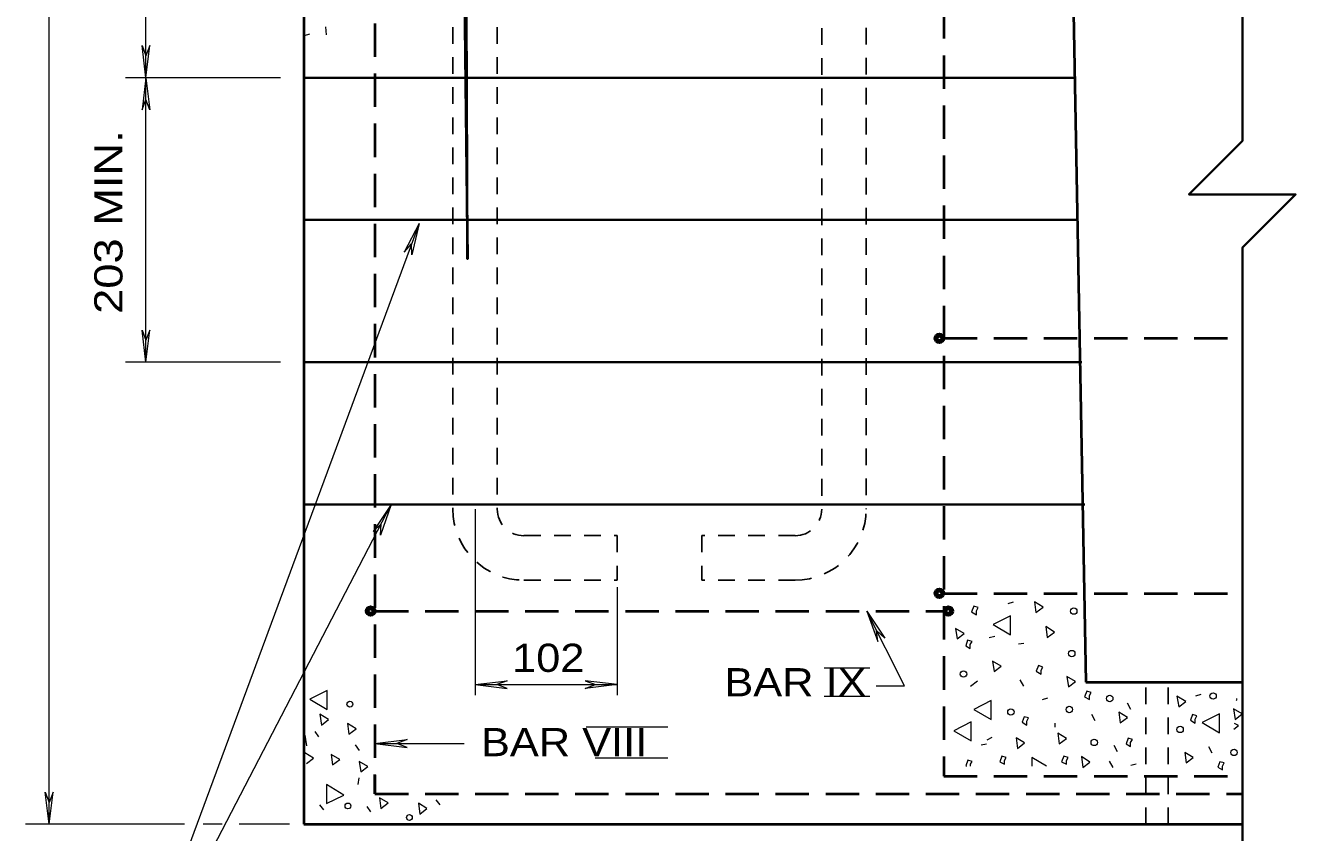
# Model space of a CAD drawing. Extents: x 312583 to 312854, y 144419 to 144597.
# Drawn here: x 312747.38 to 312781.61, y 144449.56 to 144471.31 of the extents above; entities that cross this region are included whole.
import ezdxf

# ---------------------------------------------------------------- set-up
doc = ezdxf.new("R2010")
doc.units = 0
doc.header["$LTSCALE"] = 0.3
doc.linetypes.add('MEDIUM_DASHED', pattern=[4.5, 3, -1.5])
doc.linetypes.add('SHORT_DASHED', pattern=[2.7, 1.5, -1.2])
doc.layers.add('1', color=7, linetype='Continuous', lineweight=25)
doc.layers.add('2', color=7, linetype='Continuous', lineweight=13)

msp = doc.modelspace()

# ---------------------------------------------------------------- linework, layer by layer
at = {"layer": '1', "lineweight": 40}
for p, q in [((312754.8813, 144492.4211), (312754.8813, 144449.7791)), ((312775.2517, 144491.7004), (312775.9647, 144453.6124)), ((312775.9647, 144453.6124), (312780.1813, 144453.6124)), ((312756.798, 144450.5994), (312756.798, 144451.1208)), ((312756.798, 144450.5994), (312757.626, 144450.5994)), ((312754.8813, 144449.7791), (312780.1813, 144449.7791))]:
    msp.add_line(p, q, dxfattribs=at)
at = {"layer": '1', "linetype": 'SHORT_DASHED'}
for p, q in [((312758.8987, 144491.5164), (312758.8987, 144458.2738)), ((312760.0947, 144491.5164), (312760.0947, 144458.2738)), ((312768.8423, 144489.8681), (312768.8423, 144458.2738)), ((312770.0383, 144489.8834), (312770.0383, 144458.2738)), ((312760.8153, 144457.5608), (312763.33, 144457.5608)), ((312763.33, 144457.5608), (312763.33, 144456.3571)), ((312765.607, 144457.5608), (312765.607, 144456.3571)), ((312768.1217, 144457.5608), (312765.607, 144457.5608)), ((312760.8153, 144456.3571), (312763.33, 144456.3571)), ((312768.1217, 144456.3571), (312765.607, 144456.3571)), ((312777.5823, 144449.7791), (312777.5823, 144453.5358)), ((312778.1803, 144449.7791), (312778.1803, 144453.4974))]:
    msp.add_line(p, q, dxfattribs=at)
at = {"layer": '1', "linetype": 'MEDIUM_DASHED', "lineweight": 40}
for p, q in [((312772.1313, 144490.7574), (312772.1313, 144451.0748)), ((312756.798, 144490.2668), (312756.798, 144450.5994)), ((312772.1313, 144462.8814), (312780.1813, 144462.8814)), ((312772.1313, 144456.0044), (312780.1813, 144456.0044)), ((312756.798, 144455.5291), (312772.1313, 144455.5291)), ((312772.1313, 144451.0748), (312780.1813, 144451.0748)), ((312756.798, 144450.5994), (312780.1813, 144450.5994))]:
    msp.add_line(p, q, dxfattribs=at)
at = {"layer": '1', "lineweight": 13}
for p, q in [((312754.8967, 144471.0388), (312755.0423, 144471.0848)), ((312755.464, 144471.2764), (312755.487, 144471.0618)), ((312773.864, 144455.7284), (312774.0097, 144455.7744)), ((312773.358, 144454.8161), (312773.5037, 144454.8544)), ((312774.1477, 144454.6474), (312774.2933, 144454.6628)), ((312773.036, 144453.6354), (312772.852, 144453.4974)), ((312774.186, 144453.6738), (312774.278, 144453.5051)), ((312778.924, 144453.2444), (312779.0697, 144453.2828)), ((312774.7917, 144453.1448), (312774.9373, 144453.1908)), ((312777.0763, 144453.0528), (312777.1683, 144452.8841)), ((312776.1103, 144452.7461), (312776.2023, 144452.5774)), ((312754.9043, 144452.1864), (312754.9503, 144451.8951)), ((312755.1803, 144452.2784), (312755.28, 144452.1404)), ((312775.1367, 144452.4011), (312775.1367, 144452.5084)), ((312756.2613, 144451.9181), (312756.3687, 144451.7724)), ((312773.1357, 144451.9181), (312773.2813, 144451.9488)), ((312773.3043, 144452.0561), (312773.4347, 144452.1251)), ((312776.716, 144451.9104), (312776.808, 144451.7418)), ((312779.269, 144451.8721), (312779.361, 144451.7034)), ((312774.508, 144451.5808), (312774.508, 144451.3508)), ((312774.899, 144451.3508), (312774.508, 144451.5808)), ((312772.852, 144451.3508), (312772.852, 144451.3968)), ((312776.5933, 144451.4811), (312776.6853, 144451.3124)), ((312777.176, 144451.3738), (312777.3217, 144451.4121)), ((312756.3457, 144450.8524), (312756.3687, 144451.0364)), ((312755.303, 144450.3081), (312755.4103, 144450.1701)), ((312756.5757, 144450.2621), (312756.6753, 144450.1164)), ((312758.4387, 144450.4384), (312758.546, 144450.3004))]:
    msp.add_line(p, q, dxfattribs=at)
at = {"layer": '1', "lineweight": 40}
msp.add_lwpolyline([(312758.9293, 144496.4231), (312759.2897, 144465.0204), (312759.167, 144496.3848)], dxfattribs=at)
at = {"layer": '1', "lineweight": 35}
msp.add_lwpolyline([(312780.1813, 144494.8208), (312780.1813, 144482.4621), (312778.74, 144481.0284), (312781.615, 144481.0284), (312780.1813, 144479.5871), (312780.1813, 144468.2021), (312778.74, 144466.7608), (312781.615, 144466.7608), (312780.1813, 144465.3271), (312780.1813, 144447.8624)], dxfattribs=at)
at = {"layer": '1', "lineweight": 13}
for points in [[(312757.994, 144465.9788), (312750.0999, 144444.6519), (312757.235, 144458.4041)], [(312754.9503, 144451.4198), (312755.142, 144451.5654), (312754.9043, 144451.7034)], [(312772.852, 144451.3968), (312772.898, 144451.4734), (312772.783, 144451.5118), (312772.7217, 144451.3584), (312772.7447, 144451.3508)]]:
    msp.add_lwpolyline(points, dxfattribs=at)
for points in [[(312773.013, 144455.5368), (312773.059, 144455.6211), (312772.944, 144455.6594), (312772.8827, 144455.5061), (312773.013, 144455.4294)], [(312774.6153, 144455.4908), (312774.807, 144455.6364), (312774.577, 144455.7744)], [(312773.933, 144454.8851), (312773.933, 144455.3988), (312773.4653, 144455.1611)], [(312772.4917, 144454.7778), (312772.6833, 144454.9234), (312772.4457, 144455.0614)], [(312774.922, 144454.8161), (312775.1137, 144454.9618), (312774.8837, 144455.1074)], [(312772.8443, 144454.6244), (312772.898, 144454.7088), (312772.7753, 144454.7471), (312772.7217, 144454.5938), (312772.8443, 144454.5171)], [(312773.4883, 144453.8961), (312773.68, 144454.0418), (312773.4423, 144454.1798)], [(312774.7533, 144453.9344), (312774.7993, 144454.0188), (312774.6843, 144454.0571), (312774.623, 144453.9038), (312774.7533, 144453.8271)], [(312775.4893, 144453.4821), (312775.681, 144453.6278), (312775.451, 144453.7658)], [(312755.51, 144452.8764), (312755.51, 144453.3901), (312755.0423, 144453.1524)], [(312776.0567, 144453.2521), (312776.1027, 144453.3288), (312775.9877, 144453.3671), (312775.9263, 144453.2138), (312776.0567, 144453.1448)], [(312778.464, 144452.9454), (312778.6557, 144453.0911), (312778.418, 144453.2291)], [(312773.4117, 144452.6004), (312773.4117, 144453.1141), (312772.944, 144452.8764)], [(312779.982, 144452.6081), (312780.1737, 144452.7538), (312779.9437, 144452.8918)], [(312755.3567, 144452.4548), (312755.5483, 144452.6004), (312755.3107, 144452.7461)], [(312772.8673, 144452.0254), (312772.8673, 144452.5391), (312772.3997, 144452.3014)], [(312774.37, 144452.5621), (312774.416, 144452.6464), (312774.301, 144452.6771), (312774.2473, 144452.5314), (312774.37, 144452.4548)], [(312776.8847, 144452.5161), (312777.084, 144452.6618), (312776.8463, 144452.7998)], [(312778.9087, 144452.6158), (312778.9547, 144452.7001), (312778.8397, 144452.7384), (312778.7783, 144452.5851), (312778.9087, 144452.5084)], [(312779.568, 144452.2478), (312779.568, 144452.7614), (312779.1003, 144452.5238)], [(312756.0927, 144452.2094), (312756.292, 144452.3551), (312756.0543, 144452.4931)], [(312775.244, 144451.9488), (312775.4433, 144452.0944), (312775.2057, 144452.2324)], [(312774.117, 144451.8261), (312774.3087, 144451.9718), (312774.0787, 144452.1098)], [(312777.1683, 144451.9871), (312777.2143, 144452.0638), (312777.0993, 144452.1021), (312777.0457, 144451.9488), (312777.1683, 144451.8798)], [(312755.6557, 144451.3814), (312755.8473, 144451.5271), (312755.6173, 144451.6651)], [(312773.7643, 144451.4964), (312773.8103, 144451.5808), (312773.6953, 144451.6191), (312773.6417, 144451.4658), (312773.7643, 144451.3968)], [(312775.4357, 144451.4964), (312775.4817, 144451.5808), (312775.3667, 144451.6191), (312775.3053, 144451.4658), (312775.4357, 144451.3968)], [(312775.8803, 144451.3124), (312776.072, 144451.4581), (312775.842, 144451.6038)], [(312778.6633, 144451.4351), (312778.855, 144451.5808), (312778.625, 144451.7188)], [(312756.4147, 144451.1898), (312756.6063, 144451.3354), (312756.3763, 144451.4734)], [(312779.6447, 144451.3508), (312779.6907, 144451.4351), (312779.5757, 144451.4658), (312779.522, 144451.3201), (312779.6447, 144451.2434)], [(312755.4947, 144450.8524), (312755.4947, 144450.3388), (312755.9623, 144450.5688)], [(312756.959, 144450.2008), (312757.1507, 144450.3541), (312756.9207, 144450.4921)], [(312758.0093, 144450.0551), (312758.201, 144450.2008), (312757.971, 144450.3464)]]:
    msp.add_lwpolyline(points, close=True, dxfattribs=at)
at = {"layer": '1', "lineweight": 40}
for centre, radius in [((312772.0144, 144462.8786), 0.1198), ((312772.0144, 144462.8786), 0.0838), ((312772.0144, 144462.8786), 0.0587), ((312772.0144, 144456.0054), 0.1198), ((312772.0144, 144456.0054), 0.0838), ((312772.0144, 144456.0054), 0.0587), ((312756.6811, 144455.5262), 0.1198), ((312756.6811, 144455.5262), 0.0838), ((312772.254, 144455.5262), 0.1198), ((312772.254, 144455.5262), 0.0838), ((312756.6811, 144455.5262), 0.0587), ((312772.254, 144455.5262), 0.0587)]:
    msp.add_circle(centre, radius, dxfattribs=at)
at = {"layer": '1', "lineweight": 13}
for centre, radius in [((312775.6357, 144455.5264), 0.0865), ((312775.582, 144454.3821), 0.0865), ((312772.662, 144453.8301), 0.0865), ((312776.6046, 144453.1708), 0.0865), ((312779.3904, 144453.2379), 0.0865), ((312756.1221, 144453.018), 0.0784), ((312773.9404, 144452.8076), 0.0865), ((312775.5149, 144452.8747), 0.0865), ((312778.5021, 144452.3361), 0.0865), ((312776.1877, 144451.9863), 0.0865), ((312779.9549, 144451.717), 0.0865), ((312756.0703, 144450.2734), 0.0784), ((312757.7273, 144449.9629), 0.0784)]:
    msp.add_circle(centre, radius, dxfattribs=at)
at = {"layer": '1', "linetype": 'SHORT_DASHED'}
for centre, radius, start, end in [((312760.8134, 144458.2757), 1.9167, 180, 270), ((312760.8134, 144458.2757), 0.7188, 180, 270), ((312768.1217, 144458.2757), 1.9167, 270, 0), ((312768.1217, 144458.2757), 0.7188, 270, 0)]:
    msp.add_arc(centre, radius, start, end, dxfattribs=at)
at = {"layer": '2'}
for p, q in [((312748.0197, 144449.7791), (312748.0197, 144492.9041)), ((312750.6263, 144469.9041), (312750.6263, 144492.9041)), ((312750.519, 144470.7704), (312750.6263, 144470.4944)), ((312750.6263, 144469.9041), (312750.519, 144470.7704)), ((312750.7337, 144470.7704), (312750.6263, 144470.4944)), ((312750.6263, 144469.9041), (312750.7337, 144470.7704)), ((312754.2527, 144469.9041), (312750.0743, 144469.9041)), ((312750.6263, 144469.9041), (312750.519, 144469.0378)), ((312750.6263, 144469.9041), (312750.7337, 144469.0378)), ((312750.6263, 144462.2374), (312750.6263, 144469.9041)), ((312750.519, 144469.0378), (312750.6263, 144469.3138)), ((312750.7337, 144469.0378), (312750.6263, 144469.3138)), ((312757.994, 144465.9788), (312757.5877, 144465.2044)), ((312757.994, 144465.9788), (312757.7947, 144465.1278)), ((312757.5877, 144465.2044), (312757.787, 144465.4268)), ((312757.7947, 144465.1278), (312757.787, 144465.4268)), ((312750.5189, 144463.1037), (312750.6263, 144462.8277)), ((312750.6263, 144462.2374), (312750.5189, 144463.1037)), ((312750.7336, 144463.1037), (312750.6263, 144462.8277)), ((312750.6263, 144462.2374), (312750.7336, 144463.1037)), ((312754.2527, 144462.2374), (312750.0743, 144462.2374)), ((312757.235, 144458.4041), (312756.752, 144457.6758)), ((312757.235, 144458.4041), (312756.9437, 144457.5761)), ((312759.4967, 144458.2738), (312759.4967, 144453.2598)), ((312756.752, 144457.6758), (312756.9667, 144457.8751)), ((312756.9437, 144457.5761), (312756.9667, 144457.8751)), ((312763.33, 144456.1731), (312763.33, 144453.2598)), ((312770.0537, 144455.5291), (312770.3527, 144454.7088)), ((312770.0537, 144455.5291), (312770.5443, 144454.8008)), ((312770.3527, 144454.7088), (312770.322, 144455.0001)), ((312770.5443, 144454.8008), (312770.322, 144455.0001)), ((312768.9037, 144453.9958), (312770.138, 144453.9958)), ((312759.4967, 144453.5434), (312760.363, 144453.6508)), ((312760.363, 144453.6508), (312760.087, 144453.5434)), ((312762.4637, 144453.6508), (312762.7397, 144453.5434)), ((312763.33, 144453.5434), (312762.4637, 144453.6508)), ((312759.4967, 144453.5434), (312763.33, 144453.5434)), ((312759.4967, 144453.5434), (312760.363, 144453.4361)), ((312760.363, 144453.4361), (312760.087, 144453.5434)), ((312762.4637, 144453.4361), (312762.7397, 144453.5434)), ((312763.33, 144453.5434), (312762.4637, 144453.4361)), ((312768.9037, 144453.2353), (312770.138, 144453.2353)), ((312762.4953, 144452.4088), (312764.6947, 144452.4088)), ((312756.798, 144451.9564), (312757.6643, 144452.0638)), ((312756.798, 144451.9564), (312759.2053, 144451.9564)), ((312756.798, 144451.9564), (312757.6643, 144451.8491)), ((312757.6643, 144452.0638), (312757.3883, 144451.9564)), ((312757.6643, 144451.8491), (312757.3883, 144451.9564)), ((312762.732, 144451.5686), (312764.6947, 144451.5686)), ((312747.9123, 144450.6454), (312748.0197, 144450.3694)), ((312748.0197, 144449.7791), (312747.9123, 144450.6454)), ((312748.127, 144450.6454), (312748.0197, 144450.3694)), ((312748.0197, 144449.7791), (312748.127, 144450.6454)), ((312751.6613, 144449.7791), (312747.3757, 144449.7791)), ((312752.681, 144449.7791), (312752.1673, 144449.7791)), ((312754.498, 144449.7791), (312753.141, 144449.7791))]:
    msp.add_line(p, q, dxfattribs=at)
at = {"layer": '2', "lineweight": 35}
for p, q in [((312775.658, 144469.9041), (312754.8813, 144469.9041)), ((312775.7347, 144466.0708), (312754.8813, 144466.0708)), ((312775.8573, 144462.2374), (312754.8813, 144462.2374)), ((312775.934, 144458.4041), (312754.8813, 144458.4041))]:
    msp.add_line(p, q, dxfattribs=at)
at = {"layer": '2'}
for points in [[(312770.3067, 144453.5128), (312771.0733, 144453.5128), (312770.0537, 144455.5291)], [(312780.0203, 144453.1141), (312780.0433, 144453.1524), (312780.0203, 144453.1601)], [(312779.9513, 144452.3474), (312780.074, 144452.4394), (312779.9667, 144452.5008)]]:
    msp.add_lwpolyline(points, dxfattribs=at)

# ---------------------------------------------------------------- texts
at = {"layer": '2', "width": 1.2}
msp.add_text('203 MIN.', height=0.76, rotation=90, dxfattribs=at).set_placement((312749.9926, 144463.5391))
at = {"layer": '2', "width": 1.15}
for s, p in [('102 ', (312760.4948, 144453.8875)), ('BAR IX', (312766.2165, 144453.2291)), ('BAR VIII', (312759.6562, 144451.6143))]:
    msp.add_text(s, height=0.76, dxfattribs=at).set_placement(p)

doc.saveas('drawing.dxf')
